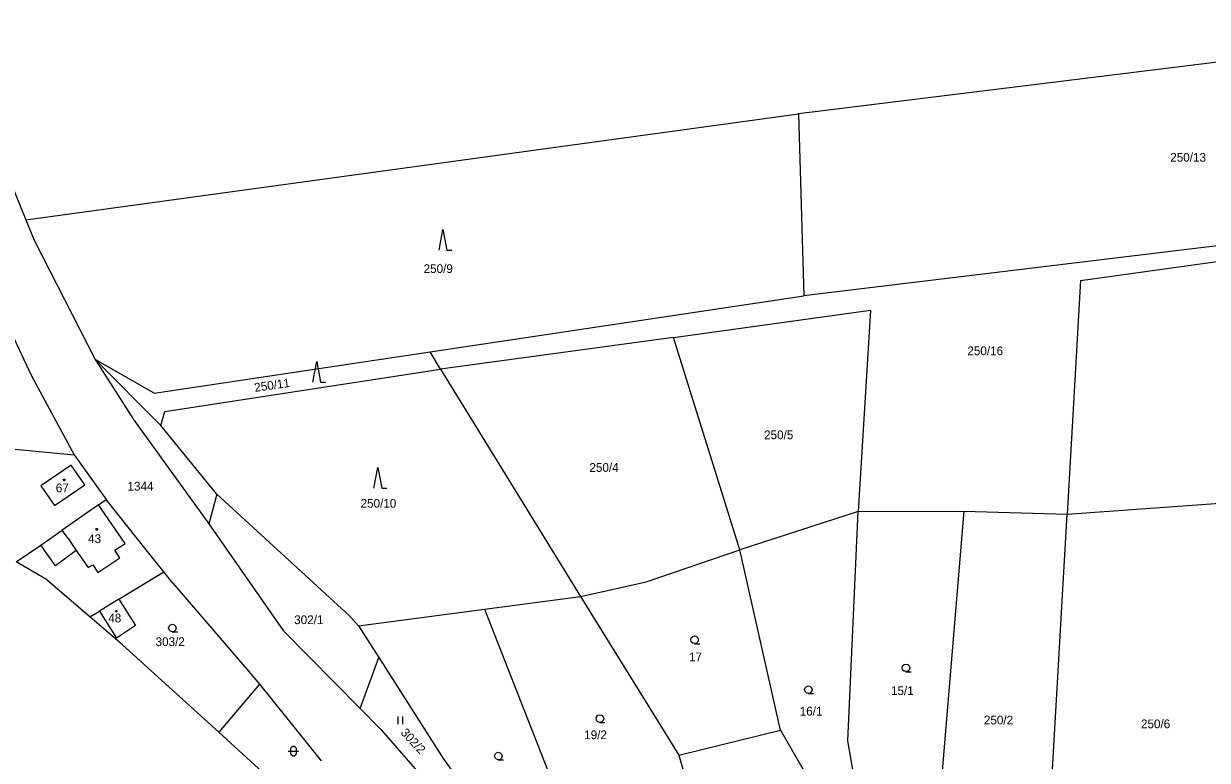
# Model space of a CAD drawing. Extents: x -852001 to -842497, y -1063614 to -1052182.
# Drawn here: x -844674.2 to -844444, y -1061361.2 to -1061217.8 of the extents above; entities that cross this region are included whole.
import ezdxf

# ---------------------------------------------------------------- set-up
doc = ezdxf.new("R2010")
doc.units = 0
for name, color, linetype in [('Default', 7, 'Continuous'), ('KN_HRANICE', 7, 'Continuous'), ('KN_KULTURY', 7, 'Continuous'), ('KN_PARCELY', 7, 'Continuous'), ('KN_SLUCKY', 7, 'Continuous')]:
    doc.layers.add(name, color=color, linetype=linetype)

# ---------------------------------------------------------------- blocks, each defined once
blk = doc.blocks.new('304')
at = {"layer": 'Default'}
blk.add_lwpolyline([(0, 0), (-0.38, 0.1), (-0.65, 0.37), (-0.75, 0.74), (-0.65, 1.11), (-0.38, 1.38), (-0.01, 1.48), (0.36, 1.38), (0.63, 1.11), (0.73, 0.73), (0.63, 0.35), (0.36, 0.08), (-0.02, -0.02), (0.98, -0.02)], dxfattribs=at)
blk = doc.blocks.new('306')
at = {"layer": 'Default'}
for p, q in [((-0.5, 1.5), (-0.5, 0)), ((0.5, 0), (0.5, 1.5))]:
    blk.add_line(p, q, dxfattribs=at)
blk = doc.blocks.new('308')
at = {"layer": 'Default'}
blk.add_lwpolyline([(-0.75, 0), (0, 4), (0.75, 0), (1.75, 0)], dxfattribs=at)
blk = doc.blocks.new('316')
at = {"layer": 'Default'}
for points in [[(-1, 1), (0.27, 1), (1, 1)], [(-0.5, 1.5), (-0.4, 1.79), (-0.15, 1.97), (0.16, 1.97), (0.41, 1.79), (0.51, 1.5), (0.51, 0.5), (0.41, 0.21), (0.16, 0.03), (-0.15, 0.03), (-0.4, 0.21), (-0.5, 0.5), (-0.5, 1.5)]]:
    blk.add_lwpolyline(points, dxfattribs=at)
blk = doc.blocks.new('402')
at = {"layer": 'Default'}
blk.add_lwpolyline([(0.09, 0.15), (0.18, 0), (0.09, -0.15), (-0.09, -0.15), (-0.18, 0), (-0.09, 0.15), (0.09, 0.15)], dxfattribs=at)

msp = doc.modelspace()

# ---------------------------------------------------------------- linework, layer by layer
at = {"layer": 'KN_HRANICE'}
for p, q in [((-844381.5, -1061217.84), (-844523.56, -1061235.4)), ((-844673.82, -1061256.03), (-844523.56, -1061235.4)), ((-844523.56, -1061235.4), (-844522.5, -1061270.83)), ((-844679.88, -1061241.1), (-844673.82, -1061256.03)), ((-844673.82, -1061256.03), (-844672.21, -1061260)), ((-844393.8, -1061255.17), (-844522.5, -1061270.83)), ((-844672.21, -1061260), (-844660.3, -1061283.17)), ((-844468.71, -1061267.83), (-844430.13, -1061262.42)), ((-844468.71, -1061267.83), (-844471.31, -1061313.26)), ((-844595.18, -1061281.72), (-844522.5, -1061270.83)), ((-844547.89, -1061278.94), (-844509.56, -1061273.56)), ((-844509.56, -1061273.56), (-844511.96, -1061312.74)), ((-844676.52, -1061278.21), (-844672.78, -1061286.23)), ((-844547.89, -1061278.94), (-844593.18, -1061285.1)), ((-844534.95, -1061320.21), (-844547.89, -1061278.94)), ((-844648.86, -1061289.77), (-844660.3, -1061283.17)), ((-844660.3, -1061283.17), (-844647.58, -1061296.05)), ((-844648.86, -1061289.77), (-844595.18, -1061281.72)), ((-844593.18, -1061285.1), (-844595.18, -1061281.72)), ((-844672.78, -1061286.23), (-844664.39, -1061301.73)), ((-844646.76, -1061293.3), (-844593.18, -1061285.1)), ((-844593.18, -1061285.1), (-844565.97, -1061329.33)), ((-844647.58, -1061296.05), (-844646.76, -1061293.3)), ((-844636.7, -1061309.42), (-844647.58, -1061296.05)), ((-844681.7, -1061300.12), (-844664.39, -1061301.73)), ((-844664.39, -1061301.73), (-844658.2, -1061310.45)), ((-844659.68, -1061311.49), (-844666.75, -1061316.38)), ((-844659.68, -1061311.49), (-844658.2, -1061310.45)), ((-844650.16, -1061320.55), (-844658.2, -1061310.45)), ((-844636.7, -1061309.42), (-844638.21, -1061315.18)), ((-844610.86, -1061333.04), (-844636.7, -1061309.42)), ((-844511.96, -1061312.74), (-844534.95, -1061320.21)), ((-844513.95, -1061357.42), (-844511.96, -1061312.74)), ((-844511.96, -1061312.74), (-844491.42, -1061312.67)), ((-844491.42, -1061312.67), (-844497.75, -1061388.86)), ((-844491.42, -1061312.67), (-844471.31, -1061313.26)), ((-844475.97, -1061394.54), (-844471.31, -1061313.26)), ((-844638.21, -1061315.18), (-844623.75, -1061335.89)), ((-844670.88, -1061319.31), (-844666.75, -1061316.38)), ((-844675.67, -1061322.54), (-844670.88, -1061319.31)), ((-844646.99, -1061324.49), (-844650.16, -1061320.55)), ((-844553.2, -1061326.42), (-844534.95, -1061320.21)), ((-844527.05, -1061355.32), (-844534.95, -1061320.21)), ((-844669.9, -1061325.92), (-844675.67, -1061322.54)), ((-844655.73, -1061329.85), (-844646.99, -1061324.49)), ((-844645.22, -1061326.74), (-844646.99, -1061324.49)), ((-844661.35, -1061333.29), (-844669.9, -1061325.92)), ((-844645.22, -1061326.74), (-844630.82, -1061343.42)), ((-844565.97, -1061329.33), (-844553.2, -1061326.42)), ((-844655.73, -1061329.85), (-844659.51, -1061332.16)), ((-844655.73, -1061329.85), (-844652.47, -1061334.93)), ((-844584.6, -1061331.79), (-844565.97, -1061329.33)), ((-844565.97, -1061329.33), (-844546.85, -1061360.21)), ((-844661.35, -1061333.29), (-844659.51, -1061332.16)), ((-844659.51, -1061332.16), (-844656.2, -1061337.41)), ((-844609.09, -1061335.03), (-844584.6, -1061331.79)), ((-844584.6, -1061331.79), (-844563.96, -1061384.43)), ((-844655.01, -1061338.74), (-844661.35, -1061333.29)), ((-844609.09, -1061335.03), (-844610.86, -1061333.04)), ((-844652.47, -1061334.93), (-844656.2, -1061337.41)), ((-844623.75, -1061335.89), (-844608.78, -1061351.11)), ((-844609.09, -1061335.03), (-844605.17, -1061341.19)), ((-844636.31, -1061355.71), (-844655.01, -1061338.74)), ((-844608.78, -1061351.11), (-844605.17, -1061341.19)), ((-844605.17, -1061341.19), (-844592.68, -1061360.84)), ((-844630.82, -1061343.42), (-844628.4, -1061346.39)), ((-844628.4, -1061346.39), (-844636.31, -1061355.71)), ((-844628.4, -1061346.39), (-844616.36, -1061361.27)), ((-844608.78, -1061351.11), (-844604.71, -1061355.25)), ((-844604.71, -1061355.25), (-844593.67, -1061367.85)), ((-844623.03, -1061367.82), (-844636.31, -1061355.71)), ((-844546.85, -1061360.21), (-844527.05, -1061355.32)), ((-844527.05, -1061355.32), (-844515.02, -1061376.12)), ((-844510.28, -1061378.35), (-844513.95, -1061357.42)), ((-844592.68, -1061360.84), (-844580.38, -1061377.63)), ((-844546.85, -1061360.21), (-844543.93, -1061370.06))]:
    msp.add_line(p, q, dxfattribs=at)
msp.add_lwpolyline([(-844665.01, -1061303.73), (-844670.88, -1061307.77), (-844668.23, -1061311.61), (-844662.36, -1061307.59)], close=True, dxfattribs=at)
at = {"layer": 'KN_SLUCKY'}
for p, q in [((-844660.3, -1061283.17), (-844652.9, -1061294.84)), ((-844652.9, -1061294.84), (-844638.21, -1061315.18)), ((-844654.51, -1061319.01), (-844659.68, -1061311.49)), ((-844471.31, -1061313.26), (-844432.89, -1061310.51)), ((-844665.6, -1061318.02), (-844666.75, -1061316.38)), ((-844665.6, -1061318.02), (-844664, -1061320.38)), ((-844668.06, -1061323.31), (-844670.88, -1061319.31)), ((-844664, -1061320.38), (-844668.06, -1061323.31)), ((-844664, -1061320.38), (-844661.66, -1061323.63)), ((-844656.51, -1061320.27), (-844654.51, -1061319.01)), ((-844655.51, -1061321.76), (-844656.51, -1061320.27)), ((-844659.79, -1061324.63), (-844655.51, -1061321.76)), ((-844661.66, -1061323.63), (-844660.79, -1061323.13)), ((-844660.79, -1061323.13), (-844659.79, -1061324.63))]:
    msp.add_line(p, q, dxfattribs=at)

# ---------------------------------------------------------------- block references
at = {"layer": 'KN_KULTURY'}
for name, p in [('308', (-844592.69, -1061261.92)), ('308', (-844617.25, -1061287.57)), ('308', (-844605.36, -1061308.21)), ('402', (-844666.36, -1061306.65)), ('402', (-844660, -1061316.24)), ('402', (-844656.2, -1061332.17)), ('304', (-844645.31, -1061336.18)), ('304', (-844543.75, -1061338.47)), ('304', (-844502.65, -1061343.92)), ('304', (-844521.63, -1061348.17)), ('306', (-844600.99, -1061354.13)), ('304', (-844562.17, -1061353.8)), ('316', (-844621.77, -1061360.38)), ('304', (-844581.92, -1061361.08))]:
    msp.add_blockref(name, p, dxfattribs=at)

# ---------------------------------------------------------------- texts
at = {"layer": 'KN_PARCELY'}
for s, p in [('250/13', (-844451.26, -1061244.7)), ('250/9', (-844596.46, -1061266.36)), ('250/16', (-844490.72, -1061282.35)), ('250/5', (-844530.25, -1061298.7)), ('250/4', (-844564.21, -1061305.05)), ('1344', (-844654.04, -1061308.69)), ('67', (-844667.99, -1061309.02)), ('250/10', (-844608.72, -1061312.02)), ('43', (-844661.71, -1061318.91)), ('48', (-844657.78, -1061334.35)), ('302/1', (-844621.63, -1061334.68)), ('303/2', (-844648.58, -1061338.95)), ('17', (-844544.84, -1061341.91)), ('15/1', (-844505.57, -1061348.48)), ('16/1', (-844523.32, -1061352.47)), ('250/2', (-844487.5, -1061354.19)), ('19/2', (-844565.23, -1061357.06)), ('250/6', (-844456.95, -1061354.94))]:
    msp.add_text(s, height=1.7, dxfattribs=at).set_placement(p)
for s, rotation, p in [('250/11', 8.136, (-844629.25, -1061289.5)), ('302/2', 312.606, (-844601.03, -1061355.89))]:
    msp.add_text(s, height=1.7, rotation=rotation, dxfattribs=at).set_placement(p)

doc.saveas('drawing.dxf')
